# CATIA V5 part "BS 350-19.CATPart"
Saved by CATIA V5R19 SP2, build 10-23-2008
Part number: BS 300-19
Bounding box of the stored display mesh (mm): x -15.868 to 15.868, y -15.868 to 15.868, z 0 to 68
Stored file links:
  C:\Users\Bora\Desktop\3D Katı model\BS serisi\BS 300\BS 300-19.CATPart
  C:\Program Files\Dassault Systemes\B19\intel_a\reffiles\standard\MetricThickPitch.txt
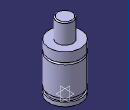
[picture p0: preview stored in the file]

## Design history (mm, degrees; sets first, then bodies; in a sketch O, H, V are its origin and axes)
Body1 (main body)
  Sketch1 on yz-plane, origin (0, 0, 0), H (0, 1, 0), V (0, 0, 1)
    point P1 (8, 67)
    point P3 (8, 67)
    point P5 (16, 38.5)
    point P6 (16, 36.5)
    point P9 (16, 38.5)
    point P14 (16, 36.5)
    line L1 (8, 67) -> (8, 48)
    arc A1 centre (7, 67) radius 1 from (8, 67) to (7, 68) ccw
    arc A2 centre (16, 37.5) radius 1 from (16, 38.5) to (16, 36.5) ccw
    line L2 (16, 0) -> (16, 4)
    line L3 (16, 38.5) -> (16, 48)
    line L4 (14.5, 7.5) -> (14.5, 4)
    line L5 (16, 7.5) -> (16, 36.5)
    line L6 (7, 68) -> (0, 68)
    point P15 (0, 68)
    line L7 (8, 48) -> (16, 48)
    line L8 (0, 0) -> (16, 0)
    line L9 (14.5, 4) -> (16, 4)
    line L10 (14.5, 7.5) -> (16, 7.5)
    coincidence: P15 V, P1 P3, P5 P9, P6 P14
    tangency: L6 A1
    horizontal: L7 H, L8 H, L9 H, L10 H
  Shaft1: profile Sketch1, axis Sketch1.V, angle 360
  Sketch2 on face of Shaft1 from Sketch1.L8, origin (0, 0, 0), H (1, 0, 0), V (0, -1, 0)
    point P1 (0, 0)
  Hole1: placed by Sketch2, at (0, 0, 0) direction (0, 0, 1), diameter 6.647, depth 4, threaded "M8", thread diameter 8, thread depth 4, pitch 1.25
